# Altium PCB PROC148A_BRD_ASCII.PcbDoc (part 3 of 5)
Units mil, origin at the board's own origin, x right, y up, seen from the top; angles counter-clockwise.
Board outline 7150 x 3764 mil, 4 copper layers (Top Layer, GND01, PWR/GND02, Bottom Layer), stack 60.96 mil thick; 312 components, 352 nets, 2206 pads, 423 vias.
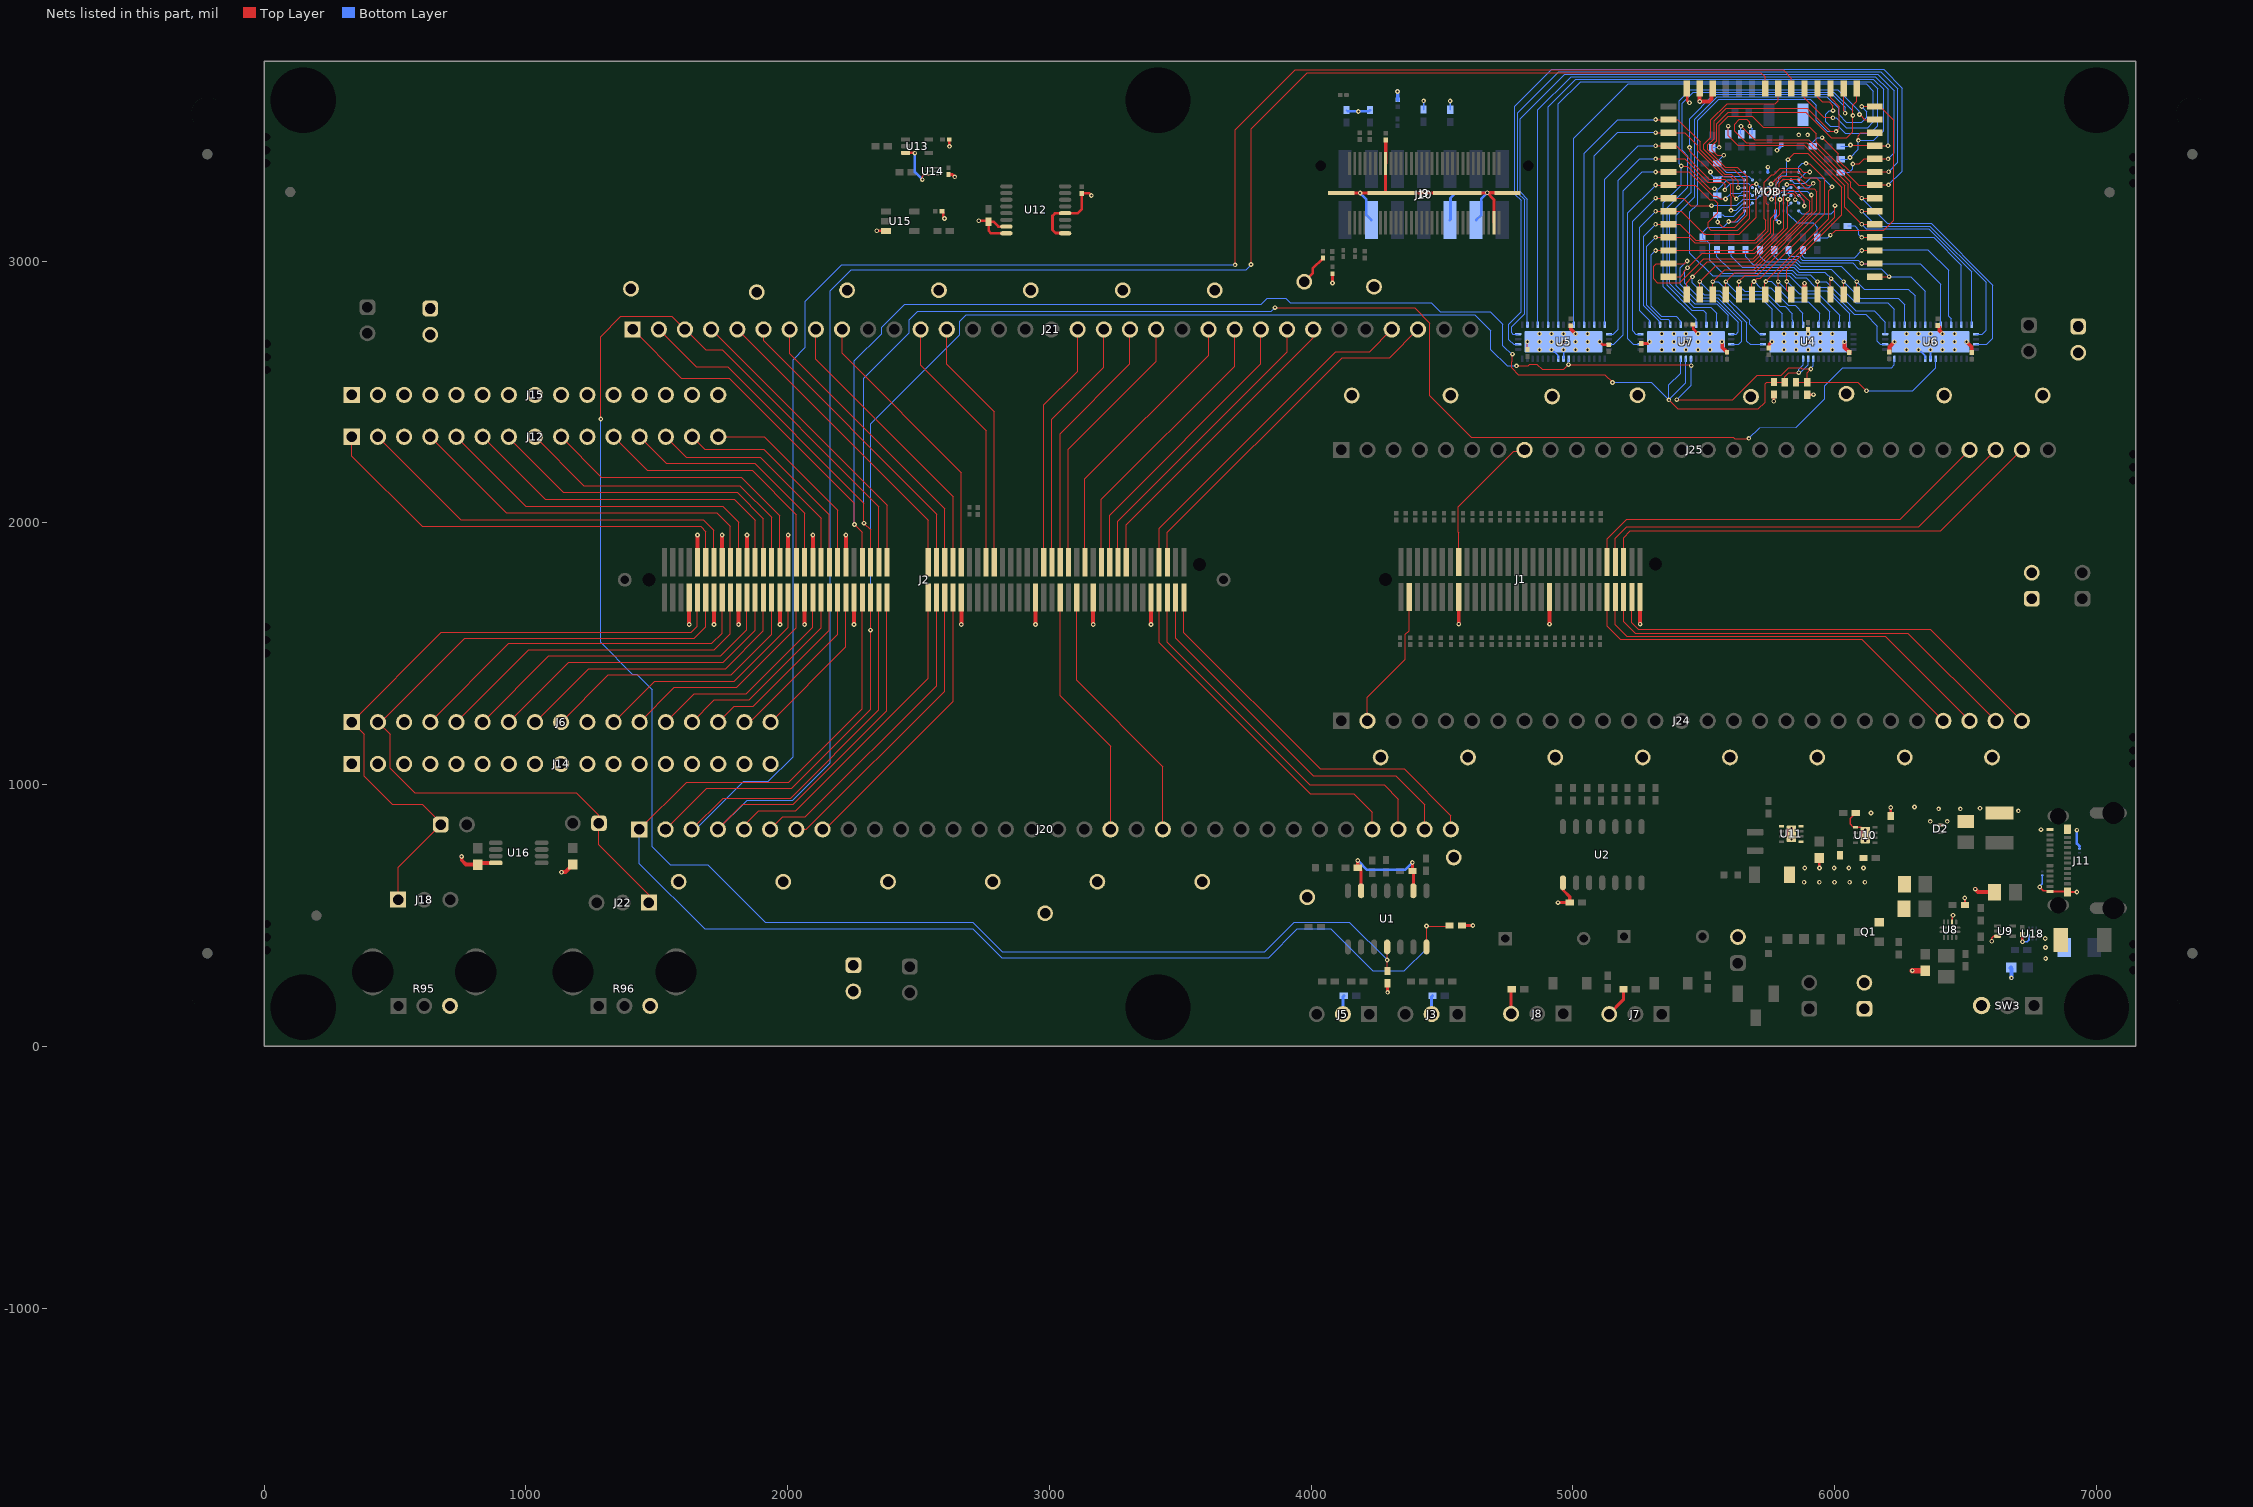
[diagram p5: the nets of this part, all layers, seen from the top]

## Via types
v1: diameter 18, hole 8, Top Layer to Bottom Layer, tented both sides, 422 vias
v2: diameter 18, hole 8, Top Layer to Bottom Layer, 1 vias

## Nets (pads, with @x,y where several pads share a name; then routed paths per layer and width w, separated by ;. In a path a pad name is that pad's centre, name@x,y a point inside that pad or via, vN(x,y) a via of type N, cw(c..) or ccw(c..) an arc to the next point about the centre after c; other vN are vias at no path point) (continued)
GND: C1.2 C2.2 C3.2 C4.2 C5.2 C6.2 C7.2 C8.2 C9.2 C10.2 C11.2 C12.2 C13.2 C14.2 C15.2 C16.2 C17.2 C18.2 C19.2 C20.2 C21.2 C22.2 C23.2 C24.2 C25.2 C26.2 C27.2 C28.2 C29.2 C30.2 C31.2 C32.2 C33.1 C34.1 C35.2 C36.2 C37.2 C38.2 C39.2 C40.2 C41.2 C43.2 C44.2 D2.2 D3.1 D4.1 J1.135 J1.157 J1.179 J2.7 J2.10 J2.13 J2.16 J2.19 J2.22 J2.29 J2.32 J2.35 J2.38 J2.46 J2.47 J2.65 J2.83 J2.97 J2.111 J3.2 J4.2 J5.2 J6.3 J6.10 J7.3 J8.3 J9.16 J9.57 J9.MP1 J9.MP2 J9.MP3 J9.MP4 J10.4 J10.10 J10.12 J11.A1 J11.A12 J11.B1 J11.B12 J12.3 J12.10 J13.1 J13.2 J14.1 J14.2 J14.3 J14.4 J14.5 J14.6 J14.7 J14.8 J14.9 J14.10 J14.11 J14.12 J14.13 J14.14 J14.15 J14.16 J14.17 J15.1 J15.2 J15.3 J15.4 J15.5 J15.6 J15.7 J15.8 J15.9 J15.10 J15.11 J15.12 J15.13 J15.14 J15.15 J17.1 J17.2 J26.1 J26.2 J27.1 J27.2 J30.1 J30.2 J31.1 J32.1 J33.1 J34.1 J35.1 J36.1 J37.1 J38.1 J39.1 J40.1 J41.1 J42.1 J43.1 J44.1 J45.1 J46.1 J47.1 J48.1 J49.1 J50.1 J51.1 J52.1 J53.1 J54.1 J55.1 J56.1 J57.1 J58.1 J59.1 J60.1 J61.1 J62.1 J63.1 J64.1 MOD1.24 MOD1.54 MOD1.55 MOD1.56 Q1.2 R8.1 R9.1 R20.1 R22.1 R25.1 R37.1 R38.1 R39.1 R52.2 R53.1 R57.2 R81.1 R82.1 R93.1 R95.3 R96.3 SW3.3 U1.2 U1.6 U2.8 U3.D1 U3.E6 U4.43 U5.9 U5.10 U5.43 U6.9 U6.10 U6.43 U7.43 U8.10 U9.3 U10.5 U10.9 U11.1 U11.4 U11.5 U11.9@5834.41,812.07 U12.7 U12.8 U12.9 U12.12 U13.3 U14.3 U15.3 U16.4 U18.3 | length 7692.2
  Top Layer w4: v1(4825.93,2691.88) 4825.93,2662.26 C15.2@4826.2,2661.98 ; C13.2@5897.7,2739.41 5898.72,2738.39 v1(5898.72,2722.39)
  Top Layer w6: v1(2514.67,3311.21) 2514.84,3311.38 2514.84,3324.49 2519.9,3329.55 U14.3@2537.8,3329.55 ; C31.2@6080,891.89 6060,871.89 6060,848.37 6069.69,838.69 6077.49,838.69 U10.5@6079.41,836.76 6100.61,836.76 6116.82,820.56 U10.9@6116.82,807.24 ; U8.10@6448.46,475.46 6448.46,494.31 6452,497.84 v1(6452,501) ; v1(6496.94,566.8) 6496.94,565 6497.64,564.3 R53.1@6497.64,540.03 ; v1(6600,402) 6600,413.94 6607.06,421 U9.3@6622,421 ; v1(6783.12,608.74) 6797.06,594.8 6819.02,594.8 J11.A1@6821.93,591.89 6886.89,591.89 J11.B12@6888.86,589.92 v1(6925,589.92)
  Top Layer w10: v1(2340.36,3115.94) 2374.83,3115.94 U15.3@2376.02,3114.75 ; U13.3@2450.71,3413.37 2485.11,3413.37 v1(2485.95,3412.53) ; C40.2@2589.95,3190.55 2590.74,3190.55 2594.01,3187.28 2594.01,3169.83 2598.99,3164.84 v1(2598.99,3162.68) ; C38.2@2617.28,3464.55 2617.76,3464.07 2617.76,3438.94 v1(2618.24,3438.46) ; v1(2730.09,3154.06) 2764.52,3154.06 R82.1@2767.9,3150.68 ; U12.8@2835.71,3106.36 2777.68,3106.36 2767.9,3116.14 R82.1@2767.9,3150.68 ; U12.7@2835.71,3131.95 2805.44,3131.95 2786.71,3150.68 R82.1@2767.9,3150.68 ; U12.9@3060.12,3106.36 3059.02,3107.46 3023.21,3107.46 3011.71,3118.96 3011.71,3172.76 3021.5,3182.55 3059.53,3182.55 U12.12@3060.12,3183.13 3108.85,3183.13 3124.03,3198.31 3124.18,3198.31 C37.2@3124.18,3258.59 3152.57,3258.59 v1(3160.27,3250.89) ; J32.1@3974.04,2921.24 4005.94,2953.14 4005.94,2971.4 4045.41,3010.87 R25.1@4045.41,3011.66 R25.1@4045.81,3011.26 ; v1(4081.37,2916.66) 4081.68,2916.97 C24.2@4081.68,2952.17 ; J31.1@4240.07,2901.87 J31.1@4240.27,2902.07 ; v1(5102.31,2691.88) 5113.65,2680.54 C14.2@5137.39,2680.54 ; C21.2@5261.18,2685.49 5286.84,2685.49 v1(5293.23,2691.88) ; MOD1.56@5434.29,3659.36 5436.69,3656.97 5436.69,3613.86 v1(5445.4,3605.15) ; C22.2@5459.09,2757.6 5459.91,2756.78 5459.91,2739.96 v1(5477.48,2722.39) ; v1(5766.99,2464.61) 5766.99,2489.72 R20.1@5767.99,2490.72 ; R22.1@5896.52,2489.95 R22.1@5896.48,2489.91 ; v1(5918.63,2489.91) R22.1@5896.48,2489.91 ; v1@5940.74,681.74 C33.1@5940.74,720 ; R93.1@6214.01,880.08 v1(6214,913) ; C43.2@6716.04,428.03 6716.62,427.44 6716.62,400.58 v1(6717.21,399.99) ; R22.1@5896.48,2489.91 5895.9,2489.91 5895.9,2489.32 R22.1@5896.48,2489.91
  Top Layer w12: C39.2@2614.29,3331.13 2614.49,3330.92 2629.33,3330.92 v1(2638.5,3321.75) ; J9.MP1@4114.75,3260.09 v1(4187,3260.1) J9.MP2@4281.17,3260.1 ; v1(4178.03,710.13) C2.2@4178.03,682.92 4181.83,682.92 4190.64,674.11 U1.6@4190.64,594.55 ; C23.2@4284.88,3462.56 4284.76,3462.44 4284.76,3373.01 J9.16@4284.63,3372.89 4284.63,3263.56 J9.MP2@4281.17,3260.1 ; R9.1@4291.3,241.38 4291.3,207.6 v1(4292.4,206.5) ; v1(4386.65,703) 4386.92,702.72 C1.2@4386.92,670.72 4390.64,667 U1.2@4390.64,594.55 ; R8.1@4576.02,461.6 v1(4617.7,461.6) ; v1(4672.6,3261) 4748.89,3261 J9.MP4@4749.79,3260.09 ; J9.57@4698.02,3147.3 4698.02,3235.58 4673.5,3260.1 J9.MP3@4557.27,3260.09 4429,3260.1 4428.79,3260.3 4428.59,3260.1 J9.MP2@4307.27,3260.09 J9.MP2@4281.17,3260.1 ; J8.3@4763.69,125 4763.69,216.03 C7.2@4766.38,218.72 ; v1(4943.17,549.33) C5.2@4987.85,549.3 4987.85,571.66 4961.97,597.54 U2.8@4961.97,625.17 ; J7.3@5138.62,123.66 5192.76,177.8 C6.2@5192.76,218.72 ; C12.2@5748.48,2667.84 5748.48,2679.83 v1(5760.53,2691.88)
  Top Layer w15: v1@754.87,725.16 755.21,724.82 755.21,711.14 772.13,694.21 C30.2@816.38,694.21 822.77,700.6 884.64,700.6 U16.4@885.16,701.12 ; v1(1135.84,665.34) 1136.42,665.91 1150.87,665.91 1167.97,683.01 1168.35,683.01 1179.55,694.21 C41.2@1179.55,694.59 ; v1(1624.09,1611.66) J2.7@1624.09,1715.73 ; J2.10@1655.59,1849.59 v1(1655.59,1953.66) ; v1(1718.58,1611.66) J2.13@1718.58,1715.73 ; J2.16@1750.07,1849.59 v1(1750.07,1953.66) ; v1(1813.07,1611.66) J2.19@1813.07,1715.73 ; J2.22@1844.56,1849.59 v1(1844.56,1953.66) ; v1(1970.55,1611.66) J2.29@1970.55,1715.73 ; J2.32@2002.04,1849.59 v1(2002.04,1953.66) ; v1(2065.04,1611.66) J2.35@2065.04,1715.73 ; J2.38@2096.53,1849.59 v1(2096.53,1953.66) ; J2.46@2222.52,1849.59 v1(2222.52,1953.66) ; v1(2254.01,1611.66) J2.47@2254.01,1715.73 ; v1(2663.46,1611.66) J2.65@2663.46,1715.73 ; v1(2946.93,1611.66) J2.83@2946.93,1715.73 ; v1(3167.4,1611.66) J2.97@3167.4,1715.73 ; v1(3387.87,1611.66) J2.111@3387.87,1715.73 ; v1(4563.78,1613) J1.135@4563.78,1717.07 ; v1(4910.24,1613) J1.157@4910.24,1717.07 ; C16.2@4991.7,2753.41 4991.7,2740.87 v1(5010.18,2722.39) ; v1(5256.69,1613) J1.179@5256.69,1717.07 ; MOD1.55@5484.29,3659.36 v1(5484.29,3609.71) 5484.65,3609.35 5520.64,3609.35 5529.79,3618.5 5529.79,3654.86 MOD1.54@5534.29,3659.36 ; v1(5569.61,2691.88) 5570.5,2690.99 5570.5,2670.48 5588.8,2652.18 C20.2@5588.8,2651.39 ; MOD1.24@5884.29,2871.96 5884.37,2872.05 v1(5884.37,2915.4) ; v1(6036.91,2691.88) 6037.8,2690.99 6037.8,2670.48 6056.1,2652.18 C11.2@6056.1,2651.39 ; C18.2@6208.54,2652.91 6208.54,2672.59 v1(6227.83,2691.88) ; C19.2@6393.6,2753.41 6399.87,2747.14 6399.87,2734.61 v1(6412.08,2722.39) ; v1(6504.21,2691.88) 6523.4,2672.69 C17.2@6523.4,2651.39 ; v1(6537.05,601) 6548.13,589.92 C26.2@6610,589.92
  Top Layer w20: v1(6296.63,289.52) 6297.45,288.7 R52.2@6346,288.7
  Bottom Layer w6: R39.1@4134.6,3577 R39.1@4139.73,3571.87 ; R37.1@4429.6,3579.24 v1(4429.6,3612.24) ; R81.1@4531,3578.7 v1(4531,3611.7) ; v1(4918.05,2661.37) 4921.25,2661.37 4942.51,2640.12 4942.51,2628.84 U5.10@4944.43,2626.92 ; U5.9@4964.12,2626.92 v1(4964.12,2661.37) ; v1(6319.96,2661.37) 6323.16,2661.37 6344.41,2640.12 6344.41,2628.84 U6.10@6346.34,2626.92 ; U6.9@6366.02,2626.92 v1(6366.02,2661.37) ; v1(6717.21,399.99) 6735.51,399.98 6741.67,406.14 6741.67,406.68 6742.18,407.19 U18.3@6742.18,415.65 ; v1(6783.12,608.74) 6783.12,611.99 6792.77,621.63 D3.1@6792.77,653.8
  Bottom Layer w7: D4.1@6935,755 6935,765.1
  Bottom Layer w10: v1(2485.95,3412.53) 2485.95,3339.93 v1(2514.67,3311.21) ; R39.1@4139.73,3571.87 v1(4180.13,3571.87) 4219.47,3571.87 R38.1@4224.6,3577 ; v1(4178.03,710.13) 4213.3,674.85 4358.5,674.85 v1(4386.65,703) ; v1(4187,3260.1) 4210.84,3236.25 4210.84,3175.92 J10.4@4230,3156.76 ; J10.10@4530,3156.76 4532.4,3159.16 4532.4,3240.33 4553.82,3261.75 4673.35,3261.75 v1(4672.6,3261) 4650,3238.4 4650,3176.76 J10.12@4630,3156.76 ; U3.D1@5744.53,3339.53 v1(5744.53,3358.93) ; U3.E6@5774.06,3191.89 5774.06,3161.79 v1(5787.22,3148.62) ; v1(6925,826.14) 6925,775.1 6935,765.1
  Bottom Layer w12: J5.2@4121.41,123.67 4121.41,190.31 C4.2@4124.78,193.67 ; J3.2@4459.94,123.67 4459.94,190.31 C3.2@4463.3,193.67 ; v1@5779.45,3423.67 5793.01,3437.23 5793.01,3442.51 C9.2@5795.28,3444.78
  Bottom Layer w15: v1(4329.7,3647.59) 4329.7,3646.78 4330.71,3645.77 C25.2@4330.71,3616.12 ; C44.2@6674.01,302 6671.66,299.65 6674.81,296.5 v1(6674.81,262.18)
  other v1: 6805.94,335.79 6805.12,378.11 6804.15,412.02 5883.4,627.24 5941.3,627.24 5999.2,627.24 6057.1,627.24 6115,627.24 5885.74,681.74 5941.81,681.74 5997.87,681.74 6053.94,681.74 6110,681.74 754.78,725.25 6116.82,785.58 5834.41,790.42 6788.01,828.11 6116.82,828.89 5834.41,833.73 6365,860 6430,860 6138.86,891.89 6701.38,900 6397.12,907.5 6480,907.5 6555,910 6305,915 4871.99,2661.37 5010.18,2661.37 5056.24,2661.37 5339.29,2661.37 5385.35,2661.37 5431.42,2661.37 5477.48,2661.37 5523.54,2661.37 5806.59,2661.37 5852.66,2661.37 5898.72,2661.37 5944.78,2661.37 5990.85,2661.37 6273.89,2661.37 6412.08,2661.37 6458.15,2661.37 4871.99,2691.88 4918.05,2691.88 4964.12,2691.88 5010.18,2691.88 5056.24,2691.88 5339.29,2691.88 5385.35,2691.88 5431.42,2691.88 5477.48,2691.88 5523.54,2691.88 5806.59,2691.88 5852.66,2691.88 5898.72,2691.88 5944.78,2691.88 5990.84,2691.88 6273.89,2691.88 6319.96,2691.88 6366.02,2691.88 6412.08,2691.88 6458.15,2691.88 4871.99,2722.39 4918.05,2722.39 4964.12,2722.39 5056.24,2722.39 5339.29,2722.39 5385.35,2722.39 5431.42,2722.39 5523.54,2722.39 5806.59,2722.39 5852.66,2722.39 5944.78,2722.39 5990.85,2722.39 6273.89,2722.39 6319.96,2722.39 6366.02,2722.39 6458.15,2722.39 5779.43,3423.67 5862.55,3482.45 5896.58,3482.45
GPIO48_MUX: MOD1.49 R78.1 U3.A6 U6.19 | length 2019.2
  Top Layer w4: v1(5594.8,3150.96) 5615.96,3150.96 5654.9,3189.9 5654.9,3311 5617,3348.9 5578.05,3348.9 5500.2,3426.75 5500.2,3446.06 5527.3,3473.16 5527.3,3539.89 5588.78,3601.37 5772.23,3601.37 5784.29,3613.43 MOD1.49@5784.29,3659.36
  Bottom Layer w4: U3.A6@5655.94,3191.89 5655.94,3178.7 5628.21,3150.96 v1(5594.8,3150.96) 5573.77,3129.93 5514.59,3129.93 5495.22,3110.56 5495.22,3087.76 5505.03,3077.95 5510.69,3077.95 5522.22,3066.42 5522.22,3003.72 5571.95,2953.99 5833.75,2953.99 5850.89,2936.85 5890.47,2936.85 5926.42,2900.9 5969.47,2900.9 6074.14,2796.23 6118.58,2796.23 6163.28,2751.53 6163.28,2693.22 6173.5,2683 6191.83,2683 U6.19@6192.79,2682.04
GPIO91: J1.123 J24.2 | length 539.3
  Top Layer w4: J24.2@4215,1244 4215,1333.95 4360.23,1479.18 4360.23,1574.13 4374.8,1588.7 J1.123@4374.8,1717.07
GPMC0_A0_MUX: MOD1.2 U3.A3 U5.34 | length 1461.5
  Top Layer w4: v1(5315.93,3540.66) 5401.27,3540.66 5486.84,3455.09 5486.84,3425.32 5579.56,3332.6 5604.8,3332.6 5631.7,3305.7 v1(5631.7,3280.6)
  Bottom Layer w4: U5.34@5042.86,2756.84 5042.86,3412.06 5171.46,3540.66 v1(5315.93,3540.66) ; v1(5631.7,3280.6) 5631.76,3280.54 U3.A3@5655.94,3280.47 U3.A3@5655.94,3280.47
GPMC0_A1_MUX: MOD1.3 U3.A4 U5.36 | length 1413.4
  Top Layer w4: v1(5315.93,3490.66) 5426.72,3490.66 5476.38,3441.01 5476.38,3422.41 5576.19,3322.6 5600.53,3322.6 5612.01,3311.13 5612.01,3250.07 5623.67,3238.41 v1(5624.2,3237.88)
  Bottom Layer w4: U5.36@5082.23,2756.84 5082.23,3402.13 5171.9,3491.8 5314.8,3491.8 v1(5315.93,3490.66) ; v1(5624.2,3237.88) 5637.27,3250.94 U3.A4@5655.94,3250.94
GPMC0_A2_MUX: MOD1.4 U3.A5 U5.38 | length 1313.1
  Top Layer w4: v1(5315.93,3440.66) MOD1.4@5365.59,3440.66 MOD1.4@5382.03,3440.66 ; MOD1.4@5382.07,3440.7 5394.53,3440.7 5521.63,3313.6 5580.9,3313.6 5602.2,3292.3 5602.2,3247.15 5604.72,3244.63 5604.72,3194.72 v1(5604.1,3194.1)
  Bottom Layer w4: U5.38@5121.6,2756.84 5121.6,3311.8 5250.46,3440.66 v1(5315.93,3440.66) ; v1(5604.1,3194.1) 5622.83,3194.1 5623.67,3194.94 5648.67,3219.94 5654.47,3219.94 U3.A5@5655.94,3221.42
GPMC0_A3_MUX: MOD1.5 U3.B3 U5.39 | length 1238.4
  Top Layer w4: v1(5315.93,3390.66) MOD1.5@5365.59,3390.66 5426.75,3390.66 5515.8,3301.61 5571.82,3301.61 5581.3,3292.13 5581.3,3272.98 v1(5580.48,3272.15)
  Bottom Layer w4: U5.39@5137.34,2721.41 5153.21,2721.41 5172.3,2740.5 5172.3,3308.2 5255.2,3391.1 5315.5,3391.1 v1(5315.93,3390.66) ; v1(5580.48,3272.15) 5580.48,3273.92 5603.55,3297 5668.94,3297 U3.B3@5685.47,3280.47
GPMC0_A4_MUX: MOD1.6 U3.B4 U5.41 | length 1203.8
  Top Layer w4: v1(5315.93,3340.66) MOD1.6@5365.59,3340.66 5443,3340.66 5535.92,3247.74 5549.87,3247.74 5559.94,3237.67 v1(5582.77,3237.67)
  Bottom Layer w4: U5.41@5137.34,2682.04 5155.64,2682.04 5193,2719.4 5193,3268.8 5264.86,3340.66 v1(5315.93,3340.66) ; v1(5582.77,3237.67) 5605.03,3259.94 5640.69,3259.94 5647.11,3266.36 5670.23,3266.36 5685.47,3251.12 U3.B4@5685.47,3250.94
GPMC0_A5_MUX: MOD1.7 U3.C3 U7.19 | length 1416
  Top Layer w4: v1(5315.93,3290.67) MOD1.7@5365.59,3290.66 5466.97,3290.67 5523.37,3234.27 5539.96,3234.27 5552.93,3221.29 5552.93,3183.97 5516.5,3147.54 5516.5,3128.5 5527.3,3117.7 5630.3,3117.7 5676.34,3163.74 5676.34,3170 5676.34,3284.65 5685.8,3294.11 5700.05,3294.11 v1(5700.8,3294.87)
  Bottom Layer w4: U7.19@5258.19,2682.04 5230.86,2682.04 5209.17,2703.73 5209.17,3183.9 v1(5315.93,3290.67) ; v1(5700.8,3294.87) 5700.8,3294.77 5715,3280.57 U3.C3@5715,3280.47
GPMC0_A6_MUX: MOD1.8 U3.C4 U7.21 | length 1005.3
  Top Layer w4: v1(5315.93,3240.67) MOD1.8@5365.59,3240.66 5420.93,3240.67 5449.7,3211.9 v1(5529.4,3211.9)
  Bottom Layer w4: U7.21@5258.19,2721.41 5240.87,2721.41 5228.27,2734.01 5228.27,3153 v1(5315.93,3240.67) ; v1(5529.4,3211.9) 5530.47,3212.97 5626.64,3212.97 5650.47,3236.8 5700.86,3236.8 U3.C4@5715,3250.94
GPMC0_A7_MUX: MOD1.9 U3.D4 U7.23 | length 1071.9
  Top Layer w4: v1(5315.93,3190.67) MOD1.9@5365.59,3190.66 5413.93,3190.67 5501.4,3103.2 5634.8,3103.2 5699.4,3167.8 v1(5699.4,3266.7)
  Bottom Layer w4: U7.23@5293.62,2756.84 5293.62,2772.5 5255.2,2810.92 5255.2,3129.93 v1(5315.93,3190.67) ; v1(5699.4,3266.7) 5728.77,3266.7 U3.D4@5744.53,3250.94
GPMC0_A8_MUX: MOD1.10 U3.H2 U7.25 | length 1330
  Top Layer w4: v1(5315.93,3140.67) MOD1.10@5365.59,3140.66 5408.13,3140.67 5468.6,3080.2 5695.27,3080.2 5736.17,3121.1 5736.17,3156.69 5730.92,3161.94 5730.92,3302.06 5759.29,3330.43 5767.56,3330.43 5791.14,3354.02 5865.78,3354.02 5880.75,3339.05 5903.68,3339.05 v1(5904.73,3340.1)
  Bottom Layer w4: v1(5315.93,3140.67) 5270.98,3095.72 5270.98,2829.82 5330.44,2770.36 5330.44,2759.39 U7.25@5332.99,2756.84 ; U3.H2@5862.64,3310 5891.69,3339.05 5903.68,3339.05 v1(5904.73,3340.1)
GPMC0_A9_MUX: MOD1.11 U3.H3 U7.27 | length 1300.8
  Top Layer w4: v1(5315.93,3090.67) MOD1.11@5365.59,3090.66 5443.99,3090.67 5464.46,3070.2 5700.88,3070.2 5745.91,3115.22 5745.91,3215.06 5739.32,3221.64 5739.32,3256.94 5755.98,3273.6 5767.99,3273.6 5777.26,3282.88 5777.26,3302.06 5799.08,3323.88 5859.57,3323.88 5894.45,3289 5908.67,3289 5916.89,3297.22 v1(5918.02,3297.22)
  Bottom Layer w4: v1(5315.93,3090.67) 5282.8,3057.53 5282.8,2830.73 5335,2778.53 5363.64,2778.53 5370.81,2771.36 5370.81,2758.39 U7.27@5372.36,2756.84 ; U3.H3@5862.64,3280.47 5901.27,3280.47 v1(5918.02,3297.22)
GPMC0_A10_MUX: MOD1.12 U3.H4 U7.29 | length 1190
  Top Layer w4: v1(5315.93,3040.67) MOD1.12@5365.59,3040.66 5687.88,3040.67 5754.91,3107.7 5754.91,3163.64 5761.27,3170 5775.19,3183.92 5775.19,3248.91 5797.07,3270.79 5841.33,3270.79 5884.09,3228.03 v1(5884.09,3210.25)
  Bottom Layer w4: v1(5315.93,3040.67) 5298.77,3023.51 5298.77,2827.48 5337.73,2788.53 5393.87,2788.53 5411.73,2770.67 U7.29@5411.73,2756.84 ; U3.H4@5862.64,3250.94 5884.09,3229.49 v1(5884.09,3210.25)
GPMC0_A11_MUX: MOD1.13 U3.H5 U7.39 | length 1433.3
  Top Layer w4: v1(5436.5,3000.8) 5436.37,3000.67 5435.42,3000.67 5425.42,2990.67 MOD1.13@5365.59,2990.67 5317.77,2990.67 5308.4,2981.3 5308.4,2931.8 5322.6,2917.6 5407.4,2917.6 5499.02,3009.22 5689.7,3009.22 5806.1,3125.61 5806.1,3170 5806.1,3247.74 5817.45,3259.09 5839.9,3259.09 5849.3,3249.7 v1(5849.3,3234.76)
  Bottom Layer w4: v1(5436.5,3000.8) 5410.67,2974.97 5410.67,2910.96 5472.43,2849.2 5550.1,2849.2 5632.15,2767.15 5632.15,2729.36 5624.2,2721.41 U7.39@5604.65,2721.41 ; v1(5849.3,3234.76) U3.H5@5862.64,3221.42
GPMC0_A12_MUX: MOD1.14 U3.G3 U7.41 | length 1151.4
  Top Layer w4: MOD1.14@5365.59,2940.67 5411.07,2940.67 5423.1,2952.7 5423.1,2959.99 v1(5437.81,2974.7) ; v1@5438.68,2973.83 5438.68,2975.57 5493.77,3030.67 5694.49,3030.67 5767,3103.18 5767,3155.09 5790.98,3179.07 v1(5790.98,3235.55)
  Bottom Layer w4: v1(5437.81,2974.7) 5427.29,2964.18 5427.29,2915.71 5482.04,2860.96 5553.12,2860.96 5644.83,2769.24 5644.83,2693.63 5633.24,2682.04 U7.41@5604.65,2682.04 ; v1(5790.98,3235.55) 5790.98,3257.13 5799.63,3265.78 5811.46,3265.78 5825.25,3279.57 5832.21,3279.57 U3.G3@5833.11,3280.47
GPMC0_A13_MUX: MOD1.15 U3.G4 U4.19 | length 1084.1
  Top Layer w4: MOD1.15@5434.29,2871.96 5434.3,2917.81 5454.38,2937.89 v1@5454.38,2942.05 ; v1(5456.46,2939.97) v1@5454.38,2942.05 ; v1(5821.4,3236.8) 5821.4,3128.19 5690.03,2996.82 5513.31,2996.82 5458.54,2942.05 v1@5454.38,2942.05
  Bottom Layer w4: v1(5456.46,2939.97) 5456.46,2917.05 5502.56,2870.96 5558.76,2870.96 5664.84,2764.89 5664.84,2693.68 5676.48,2682.04 U4.19@5725.49,2682.04 ; v1(5821.4,3236.8) 5821.4,3239.23 U3.G4@5833.11,3250.94
GPMC0_A14_MUX: MOD1.16 U3.F3 U4.21 | length 1081.3
  Top Layer w4: MOD1.16@5484.29,2871.96 v1(5484.29,2921.62) 5545.02,2982.35 5692.27,2982.35 5879.93,3170 5890,3180.07 5904.27,3194.34 5904.27,3227.88 5890,3242.15 5839.16,3292.98 v1(5817.17,3292.98)
  Bottom Layer w4: v1(5484.29,2921.62) 5518.79,2887.12 5561.39,2887.12 5674.84,2773.68 5674.84,2759.7 5713.13,2721.41 U4.21@5725.49,2721.41 ; U3.F3@5803.58,3280.47 5804.57,3280.47 5817.08,3292.98 v1(5817.17,3292.98)
GPMC0_A15_MUX: MOD1.17 U3.F4 U4.23 | length 1052.7
  Top Layer w4: MOD1.17@5534.29,2871.96 v1(5534.29,2921.62) 5579.51,2966.84 5690.91,2966.84 5913.27,3189.2 5913.27,3249.86 v1(5910.65,3252.48)
  Bottom Layer w4: v1(5534.29,2921.62) 5554.45,2921.62 5620.49,2855.58 5721.72,2855.58 5760.92,2816.38 U4.23@5760.92,2756.84 ; U3.F4@5803.58,3250.94 5813.41,3250.94 5828.67,3266.2 5890,3266.2 5895.86,3266.2 5909.59,3252.48 v1(5910.65,3252.48)
GPMC0_A16_MUX: MOD1.18 U3.E4 U4.25 | length 1155.3
  Top Layer w4: MOD1.18@5584.29,2871.96 v1(5584.3,2921.5) 5618.27,2955.47 5693.68,2955.47 5932.12,3193.91 5932.12,3264.69 5921.3,3275.51 5890,3275.51 5889.73,3275.51 5852.62,3312.62 5803.69,3312.62 5788.02,3296.95 5788.02,3277.3 5759.18,3248.45 5759.18,3236.23 v1(5758.85,3235.8)
  Bottom Layer w4: v1(5584.3,2921.5) 5633.84,2871.97 5727.84,2871.97 5800.29,2799.51 U4.25@5800.29,2756.84 ; v1@5758.88,3235.8 U3.E4@5774.03,3250.94
GPMC0_A17_MUX: MOD1.19 U3.D3 U4.27 | length 1137.8
  Top Layer w4: MOD1.19@5634.29,2871.96 v1(5634.3,2921.5) 5634.3,2922.51 5658.22,2946.43 5703.58,2946.43 5945.28,3188.13 5945.28,3303.3 5929.92,3318.66 5883.74,3318.66 5860.96,3341.44 5802.52,3341.44 5756.9,3295.82 v1(5756.9,3294.87)
  Bottom Layer w4: v1(5634.3,2921.5) 5634.3,2905.26 5655.46,2884.1 5733.37,2884.1 5789.84,2827.63 5810.55,2827.63 5838.47,2799.7 5838.47,2776.03 5839.66,2774.84 U4.27@5839.66,2756.84 ; U3.D3@5744.53,3280.47 5756.9,3292.85 v1(5756.9,3294.87)
GPMC0_A18_MUX: MOD1.20 U3.H1 U4.29 | length 995
  Top Layer w4: MOD1.20@5684.29,2871.96 5684,2872.26 5684,2912.93 5691.75,2920.67 v1(5691.75,2922.27) ; v1@5692.59,2922.27 5704.6,2934.28 5715.18,2934.28 5962.11,3181.21 5962.11,3314.97 5905.16,3371.92 5891.65,3371.92 v1(5890.16,3373.41)
  Bottom Layer w4: v1(5691.75,2922.27) 5715.63,2898.39 5755.78,2898.39 5823.21,2830.96 5848.38,2830.96 5878.63,2800.71 5878.63,2757.25 U4.29@5879.03,2756.84 ; U3.H1@5862.64,3339.53 5862.64,3359.74 5876.31,3373.41 v1(5890.16,3373.41)
GPMC0_A19_MUX: MOD1.21 U3.G2 U4.32 | length 1007.4
  Top Layer w4: MOD1.21@5734.29,2871.96 5732.99,2873.27 5732.99,2914.62 5736.85,2918.48 v1(5736.85,2922.27) 5976.74,3162.16 5976.74,3269.57 5989.75,3282.57 v1(5989.75,3283.87)
  Bottom Layer w4: v1(5736.85,2922.27) 5756.84,2922.27 5834.81,2844.3 5899.69,2844.3 5943.36,2800.64 5943.36,2776.71 5941.01,2774.37 5941.01,2759.76 U4.32@5938.09,2756.84 ; U3.G2@5833.11,3310 5846.11,3297 5887,3297 5909.04,3319.04 5953.41,3319.04 5988.58,3283.87 v1(5989.75,3283.87)
GPMC0_A20_MUX: MOD1.22 U3.H6 U4.34 | length 890.8
  Top Layer w4: MOD1.22@5784.29,2871.96 v1(5784.3,2921.5) 5784.3,2951.75 6000.88,3168.34 v1(6000.88,3211.88)
  Bottom Layer w4: v1(5784.3,2921.5) 5845.9,2859.9 5926.89,2859.9 5981.1,2805.69 5981.1,2777.89 5977.87,2774.65 5977.87,2757.25 U4.34@5977.46,2756.84 ; U3.H6@5862.64,3191.89 5862.98,3191.89 5874.57,3180.3 5986.24,3180.3 6000.88,3194.95 v1(6000.88,3211.88)
GPMC0_A21_MUX: MOD1.23 U3.E3 U4.36 | length 1203.9
  Top Layer w4: v1(5821.5,3387.7) 5845.86,3412.06 5897.55,3412.06 6026.87,3282.74 6026.87,3177.19 5816.8,2967.12 v1(5816.8,2922.27) 5816.8,2889.47 MOD1.23@5834.29,2871.96
  Bottom Layer w4: U3.E3@5774.06,3280.47 5775.13,3281.55 5775.13,3292.33 5787.2,3304.4 5787.2,3317.68 5795.01,3325.49 5812.14,3325.49 5817.37,3330.72 5817.37,3379.78 5821.5,3383.91 v1(5821.5,3387.7) ; v1(5816.8,2922.27) 5864.56,2874.51 5937.87,2874.51 6018.88,2793.51 ; U4.36@6016.83,2756.84 6018.88,2758.89 6018.88,2777.87 ; 6018.86,2777.89 6018.86,2793.49
GPMC0_AD0_MUX: MOD1.25 R12.2 U6.21 | length 867.3
  Top Layer w4: MOD1.25@5934.29,2871.96 v1(5934.29,2921.62)
  Bottom Layer w4: R12.2@5550.01,3042.66 5550.01,3017.36 5602.07,2965.31 5837.24,2965.31 5854.77,2947.77 5907.41,2947.77 5933.56,2921.62 5967.78,2921.62 6079.96,2809.44 6150.76,2809.44 6192.79,2767.41 U6.21@6192.79,2721.41
GPMC0_AD1_MUX: MOD1.26 R48.2 U6.23 | length 856.8
  Top Layer w4: MOD1.26@5984.29,2871.96 5982.38,2873.87 5982.38,2925.17 5986.55,2929.35 v1(5986.55,2933.13)
  Bottom Layer w4: R48.2@5604.8,3042.66 5604.8,3017.75 5646.65,2975.9 5843.7,2975.9 5861.83,2957.77 5961.92,2957.77 v1@5987.78,2931.91 ; v1(5986.55,2933.13) 5987.99,2933.13 6079.52,2841.6 6203.1,2841.6 6228.22,2816.48 U6.23@6228.22,2756.84
GPMC0_AD2_MUX: MOD1.27 R59.2 U6.25 | length 836.8
  Top Layer w4: MOD1.27@6034.29,2871.96 v1(6034.29,2921.62)
  Bottom Layer w4: R59.2@5659.59,3042.66 5659.59,3015.91 5688.46,2987.03 5847.32,2987.03 5864.86,2969.49 5986.42,2969.49 v1(6034.29,2921.62) 6097.71,2858.2 6243.2,2858.2 6267.6,2833.8 U6.25@6267.6,2756.84
GPMC0_AD3_MUX: MOD1.28 R60.2 U6.27 | length 838.8
  Top Layer w4: MOD1.28@6084.29,2871.96 v1(6084.29,2921.62)
  Bottom Layer w4: R60.2@5714.38,3042.66 5714.38,3019.13 5735.7,2997.8 5851.1,2997.8 5867.92,2980.98 6024.93,2980.98 v1(6084.29,2921.62) 6113.71,2892.2 6281.6,2892.2 6306.97,2866.84 U6.27@6306.97,2756.84
GPMC0_AD4_MUX: MOD1.29 R61.2 U6.29 | length 839.7
  Top Layer w4: MOD1.29@6152.99,2940.66 6153.06,2940.6 v1(6208.1,2940.6)
  Bottom Layer w4: R61.2@5769.17,3042.66 5769.17,3018.67 5780.04,3007.8 5854.39,3007.8 5868.71,2993.48 6069.14,2993.48 6090.83,2971.79 6176.91,2971.79 v1(6208.1,2940.6) 6290.5,2940.6 6346.34,2884.76 U6.29@6346.34,2756.84
GPMC0_AD5_MUX: MOD1.30 R62.2 U6.32 | length 851.8
  Top Layer w4: v1(6103.33,2990.67) MOD1.30@6152.99,2990.66
  Bottom Layer w4: R62.2@5823.95,3042.66 5823.95,3022.76 5828.92,3017.8 5862.07,3017.8 5876.16,3003.72 6090.28,3003.72 v1(6103.33,2990.67) 6326.33,2990.67 6405.39,2911.61 U6.32@6405.39,2756.84
GPMC0_AD6_MUX: MOD1.31 R63.2 U6.34 | length 889.6
  Top Layer w4: v1(6103.33,3040.67) MOD1.31@6152.99,3040.66
  Bottom Layer w4: R63.2@5878.74,3042.66 5878.74,3019.01 5884.34,3013.42 6076.09,3013.42 v1(6103.33,3040.67) 6162.87,3040.67 6166.2,3044 6356.3,3044 6435.74,2964.56 6435.74,2789.79 6444.76,2780.77 U6.34@6444.76,2756.84
GPMC0_AD7_MUX: MOD1.32 R64.2 U6.36 | length 785.1
  Top Layer w4: v1(6103.33,3090.67) MOD1.32@6152.99,3090.66
  Bottom Layer w4: R64.2@6048.9,3134.19 6077.21,3134.19 6092.73,3118.67 6092.73,3101.27 v1(6103.33,3090.67) 6378.51,3090.67 6484.13,2985.04 U6.36@6484.13,2756.84
GPMC0_AD8_MUX: MOD1.33 R65.2 U6.38 | length 1513.2
  Top Layer w4: v1(5593.26,3515.49) 5593.26,3479.41 5630.13,3442.55 5883.89,3442.55 6038.9,3287.53 6038.9,3205.1 v1(6103.33,3140.67) MOD1.33@6152.99,3140.66
  Bottom Layer w4: v1(5593.26,3515.49) 5593.26,3485.2 R65.2@5593.58,3484.87 ; v1(6103.33,3140.67) 6120.3,3123.7 6359.62,3123.7 6523.5,2959.82 U6.38@6523.5,2756.84
GPMC0_AD9_MUX: MOD1.34 R66.2 U6.39 | length 1656.1
  Top Layer w4: v1(5675.28,3515.49) 5675.28,3531.17 5664.6,3541.86 5635.65,3541.86 5617.39,3523.6 5617.39,3496.46 5661.3,3452.55 5893.49,3452.55 6051.9,3294.14 6051.9,3242.1 v1(6103.33,3190.67) MOD1.34@6152.99,3190.66
  Bottom Layer w4: v1(5675.28,3515.49) 5684.94,3505.83 R66.2@5684.94,3485.14 ; v1(6103.33,3190.67) 6160.3,3133.7 6363.76,3133.7 6578.84,2918.62 6578.84,2736.29 6563.96,2721.41 U6.39@6539.25,2721.41
GPMC0_AD10_MUX: MOD1.35 R67.2 U6.41 | length 1583.7
  Top Layer w4: v1(5641.67,3515.03) 5642.59,3515.03 5694.7,3462.92 5900.59,3462.92 6061.9,3301.61 6061.9,3282.1 v1(6103.33,3240.67) MOD1.35@6152.99,3240.66
  Bottom Layer w4: v1(5641.67,3515.03) 5641.67,3486.48 R67.2@5643.28,3484.87 ; v1(6103.33,3240.67) 6103.33,3240.32 6199.96,3143.7 6367.9,3143.7 6604.5,2907.1 6604.5,2704.9 6581.64,2682.04 U6.41@6539.25,2682.04
GPMC0_AD11_MUX: MOD1.36 R68.2 U5.19 | length 3825.2
  Top Layer w4: v1(5558.79,3434.57) 5558.79,3518.9 5594.05,3554.16 5684.4,3554.16 5727.22,3511.34 5905.02,3511.34 5929.14,3487.23 5929.14,3453.62 6092.1,3290.67 MOD1.36@6152.99,3290.66 6153.82,3291.5 v1(6205.1,3291.5)
  Bottom Layer w4: U5.19@4790.89,2682.04 4790.71,2682.22 4773.08,2682.22 4755.67,2699.63 4755.67,2758.67 4802.8,2805.8 4802.8,3231.58 4778.58,3255.8 4778.58,3592.2 4918.38,3732 6186.86,3732 6257.69,3661.17 6257.69,3344.09 v1(6205.1,3291.5) ; R68.2@5531.88,3431.21 5535.24,3434.57 v1(5558.79,3434.57)
GPMC0_AD12_MUX: MOD1.37 R69.2 U5.21 | length 3155.4
  Top Layer w4: v1(5952.1,3471.8) 6014.08,3409.83 6014.08,3385.7 6059.11,3340.67 MOD1.37@6152.99,3340.66 6153.82,3341.5 v1(6206.1,3341.5)
  Bottom Layer w4: U5.21@4790.89,2721.41 4770.69,2721.41 4765.67,2726.43 4765.67,2749.27 4815,2798.6 4815,3233.52 4788.58,3259.94 4788.58,3566.08 4945.5,3723 6176.09,3723 6241.4,3657.69 6241.4,3376.8 v1(6206.1,3341.5) ; R69.2@5916.11,3438.83 5916.25,3438.97 5916.25,3454.3 5933.76,3471.8 v1(5952.1,3471.8)
GPMC0_AD13_MUX: MOD1.38 R70.2 U5.23 | length 2806.8
  Top Layer w4: v1(6069.35,3371.38) 6093.53,3371.38 6112.81,3390.67 MOD1.38@6152.99,3390.66 6153.12,3390.8 v1(6204.1,3390.8)
  Bottom Layer w4: U5.23@4826.32,2756.84 4826.32,3236.34 4798.58,3264.08 4798.58,3543.82 4968.76,3714 6165.14,3714 6227.5,3651.64 6227.5,3414.2 v1(6204.1,3390.8) ; R70.2@6023.44,3339.05 6054.96,3339.05 6069.35,3353.44 v1(6069.35,3371.38)
GPMC0_AD14_MUX: MOD1.39 R71.2 U5.25 | length 2630.5
  Top Layer w4: v1(6060.2,3443.42) 6061.23,3442.39 6151.27,3442.39 MOD1.39@6152.99,3440.66 ; MOD1.39@6152.99,3440.66 v1(6203.6,3440.7)
  Bottom Layer w4: U5.25@4865.69,2756.84 4865.69,3577.7 4992.99,3705 6154.6,3705 6203.6,3656 v1(6203.6,3440.7) ; R71.2@6023.46,3438.29 6023.89,3438.73 6051.72,3438.73 6056.41,3443.42 v1(6060.2,3443.42)
GPMC0_AD15_MUX: MOD1.40 R72.2 U5.27 | length 2646.1
  Top Layer w4: v1(6090.34,3461.26) 6090.34,3479.78 6100.31,3489.75 6152.07,3489.75 MOD1.40@6152.99,3490.66
  Bottom Layer w4: U5.27@4905.06,2756.84 4905.06,3589.06 5011,3695 6147.43,3695 6186.75,3655.68 6186.75,3498.55 6149.46,3461.26 v1(6090.34,3461.26) 6090.34,3427.19 v1(6058.64,3395.48) 6054.85,3395.48 6048.25,3388.88 R72.2@6022.89,3388.88
GPMC0_BE0N_CLE_MUX: MOD1.43 R76.1 U3.A1 U7.34 | length 2775.8
  Top Layer w4: v1(5576.28,3404.55) 5550.86,3404.55 5532.21,3423.2 5532.21,3442.87 5548.74,3459.41 5548.74,3525.27 5592.71,3569.24 5888.83,3569.24 5987.57,3470.49 6046.93,3470.49 6069.7,3493.26 6069.7,3555.99 v1(6069.13,3556.55) 6069.13,3595.13 6084.29,3610.29 MOD1.43@6084.29,3659.36
  Bottom Layer w4: U7.34@5510.16,2756.84 5510.16,2801.34 5498.42,2813.08 5454.16,2813.08 5359.88,2907.36 5359.88,3204.07 5438.56,3282.75 5438.56,3400.69 5416.65,3422.6 5416.65,3603.1 5459.56,3646 5995.57,3646 6068.02,3573.55 6068.02,3557.67 v1(6069.13,3556.55) ; v1(5576.28,3404.55) 5551.24,3379.51 R76.1@5551.24,3373.4 5585.12,3339.53 U3.A1@5655.94,3339.53
GPMC0_BE1N_MUX: MOD1.44 R77.1 U3.B2 U7.36 | length 2022.3
  Top Layer w4: v1(5445.45,3434.5) 5446.96,3432.99 5446.96,3419.5 v1(5525.87,3340.58) ; MOD1.44@6034.29,3659.36 6034.29,3574.39 6040.08,3568.61 v1(6040.08,3564.82)
  Bottom Layer w4: v1(5525.87,3340.58) 5528.55,3337.91 5528.55,3330.65 5547.31,3311.9 R77.1@5551.24,3311.9 5562.94,3323.6 5671.87,3323.6 U3.B2@5685.47,3310 ; U7.36@5549.53,2756.84 5549.53,2800.23 5526.07,2823.68 5461.27,2823.68 5370.81,2914.14 5370.81,3181.59 5452.14,3262.91 5452.14,3425.16 5445.45,3431.84 5445.45,3544.18 5538.27,3637 5990.43,3637 6040.08,3587.35 v1(6040.08,3564.82)
GPMC0_CSN0_MUX: MOD1.45 R73.1 U3.B5 U4.38 | length 3409
  Top Layer w4: v1(5552.7,3149.6) 5552.7,3147.59 5571.62,3128.67 5617.47,3128.67 5665.89,3177.09 5665.89,3321.61 5628.6,3358.9 5580.98,3358.9 5514.93,3424.95 5514.93,3443.98 5539,3468.05 5539,3536.76 5586.56,3584.31 5895.11,3584.31 5983.79,3495.63 v1(6005.52,3495.63) 6005.91,3495.63 6016.98,3506.7 6016.98,3590.59 5984.29,3623.28 MOD1.45@5984.29,3659.36
  Bottom Layer w4: v1(5552.7,3149.6) 5552.7,3174.94 R73.1@5551.14,3176.5 5572.62,3176.5 5578.42,3170.7 5614.59,3170.7 5648.89,3205 5669.06,3205 U3.B5@5685.47,3221.42 ; v1(6005.52,3495.63) 5972.18,3495.63 5929.78,3538.03 5929.78,3595.22 5906,3619 5556.39,3619 5476.18,3538.79 5476.18,3217.23 5447.09,3188.14 5447.09,3031 5534.85,2943.24 5827.2,2943.24 5883.32,2887.12 5969.11,2887.12 6056.6,2799.62 6056.6,2757.25 U4.38@6056.2,2756.84
GPMC0_OEN_REN_MUX: MOD1.41 R75.1 U3.A2 U7.32 | length 2079.2
  Top Layer w4: v1(5413.9,3363.2) 5436.6,3363.2 5523.17,3276.63 v1(5541.09,3276.63) ; v1(6094.73,3560.33) 6114.39,3540.67 MOD1.41@6152.99,3540.66
  Bottom Layer w4: U7.32@5470.79,2756.84 5470.79,2777.6 5345.91,2902.48 5345.91,3222.63 5413.9,3290.62 5413.9,3364.07 5405.43,3372.54 5405.43,3612.88 5447.55,3655 6011.35,3655 6093.77,3572.58 6093.77,3561.28 v1(6094.73,3560.33) ; v1(5541.09,3276.63) 5543.13,3276.63 5543.91,3275.85 5544.64,3276.57 5556.44,3276.57 5589.86,3310 U3.A2@5655.94,3310 ; v1@5543.76,3275.7 5551.24,3268.21 R75.1@5551.24,3250.4
GPMC0_WAIT0_MUX: MOD1.47 U5.32 | length 2426.4
  Top Layer w4: MOD1.47@5884.29,3659.36 5884.29,3623.4 5958.75,3548.94 5991.78,3548.94 v1(5993.04,3547.68)
  Bottom Layer w4: U5.32@5003.49,2756.84 5003.49,3469.04 5211.45,3677 6120.04,3677 6148,3649.04 6148,3532.91 6125.42,3510.33 6043.82,3510.33 6006.46,3547.68 v1(5993.04,3547.68)
GPMC0_WEN_MUX: MOD1.42 R74.1 U3.G5 U7.38 | length 2815.6
  Top Layer w4: v1(5983.4,3099.02) 6003.17,3118.79 6187.58,3118.79 6224.97,3156.19 6224.97,3537.18 6171.49,3590.67 MOD1.42@6152.99,3590.66 v1(6103.33,3590.67)
  Bottom Layer w4: U7.38@5588.9,2756.84 5588.9,2763.73 U7.38@5591.82,2766.65 ; U7.38@5591.87,2766.65 5594.21,2769 5594.21,2792.36 5550.34,2836.24 5465.56,2836.24 5395.43,2906.38 5395.43,3175.21 5465.34,3245.13 5465.34,3542.1 5551.25,3628 5970.06,3628 6015,3583.06 6015,3560.6 6044.85,3530.75 6103.88,3530.75 6122.21,3549.09 6122.21,3571.32 6103.33,3590.2 v1(6103.33,3590.67) ; U3.G5@5833.11,3221.42 5819.1,3207.41 5819.1,3183.42 5856.52,3146 5917.69,3146 5933.53,3130.16 R74.1@5933.53,3089.9 5974.28,3089.9 v1(5983.4,3099.02)
GPMC0_WPN_MUX: MOD1.46 U5.29 | length 2666.4
  Top Layer w4: MOD1.46@5934.29,3659.36 5934.29,3625.95 5952.35,3607.89 5978.65,3607.89 5993.24,3593.31 v1(5993.24,3574.66)
  Bottom Layer w4: U5.29@4944.43,2756.84 4944.29,2756.99 4944.29,3600.9 5029.39,3686 6136.79,3686 6164.29,3658.5 6164.29,3517.93 6135.7,3489.34 6040.4,3489.34 6014.34,3515.41 5982.97,3515.41 5965.07,3533.31 5965.07,3560.51 5979.22,3574.66 v1(5993.24,3574.66)
HSEC_41: J2.41 J6.15 | length 695.9
  Top Layer w4: J6.15@1735,1239 1795.56,1299.56 1869.46,1299.56 2159.52,1589.62 J2.41@2159.52,1715.73
HSEC_43: J2.43 J6.16 | length 636.6
  Top Layer w4: J6.16@1835,1239 1856.11,1239 2191.02,1573.91 J2.43@2191.02,1715.73
HSEC_44: J2.44 J12.15 | length 771.4
  Top Layer w4: J12.15@1735,2329 1846,2329 1911,2329 2191.02,2048.98 J2.44@2191.02,1849.59
HSEC_45: J2.45 J6.17 | length 595.8
  Top Layer w4: J6.17@1935,1239 2222.52,1526.52 J2.45@2222.52,1715.73
HSEC_66: J2.66 J21.9 | length 1078.1
  Top Layer w4: J21.9@2207.95,2739 2207.95,2647.72 2663.46,2192.21 J2.66@2663.46,1849.59
HSEC_88: J2.88 J21.19 | length 971.4
  Top Layer w4: J2.88@3009.92,1849.59 3009.92,2396.55 3207.95,2594.58 J21.19@3207.95,2739
HSEC_96: J2.96 J21.23 | length 1084.9
  Top Layer w4: J2.96@3135.9,1849.59 3135.9,2168.26 3607.95,2640.31 J21.23@3607.95,2739
HSEC_113: J2.113 J20.29 | length 1321.9
  Top Layer w4: J2.113@3419.37,1715.73 3419.37,1542.07 3996.44,965 4163.6,965 4233.54,895.06 J20.29@4233.54,829
HSEC_114: J2.114 J21.30 | length 1333
  Top Layer w4: J2.114@3419.37,1849.59 3420,1850.22 3420,1980 4094.56,2654.56 4223.51,2654.56 J21.30@4307.95,2739
HSEC_115: J2.115 J20.30 | length 1418.1
  Top Layer w4: J2.115@3450.86,1715.73 3450.86,1544.52 3995.38,1000 4278.3,1000 4333.54,944.76 J20.30@4333.54,829
HSEC_116: J2.116 J21.31 | length 1392.4
  Top Layer w4: J2.116@3450.86,1849.59 3450.86,1963.88 4117.87,2630.89 4299.84,2630.89 J21.31@4407.95,2739
HSEC_117: J2.117 J20.31 | length 1464.6
  Top Layer w4: J2.117@3482.36,1715.73 3482.36,1560.05 4008.41,1034 4322.3,1034 4433.54,922.76 J20.31@4433.54,829
HSEC_119: J2.119 J20.32 | length 1496.6
  Top Layer w4: J2.119@3513.85,1715.73 3513.85,1581.15 4035,1060 4355.16,1060 4533.54,881.62 J20.32@4533.54,829
HSEC_136: J1.136 J25.8 | length 555.2
  Top Layer w4: J1.136@4563.78,1850.93 4563.78,1962.74 4561.86,1964.66 4561.86,2062.55 4773.04,2273.73 4809.73,2273.73 J25.8@4815,2279
HSEC_171: J1.171 J24.24 | length 1546
  Top Layer w4: J1.171@5130.71,1717.07 5130.71,1604.83 5180.79,1554.75 6104.25,1554.75 J24.24@6415,1244
HSEC_172: J1.172 J25.25 | length 1613.6
  Top Layer w4: J1.172@5130.71,1850.93 5130.71,1939.62 5205.25,2014.16 6250.16,2014.16 J25.25@6515,2279
HSEC_173: J1.173 J24.25 | length 1611.4
  Top Layer w4: J1.173@5162.2,1717.07 5162.2,1610.09 5205.77,1566.52 6192.48,1566.52 J24.25@6515,1244
HSEC_174: J1.174 J25.26 | length 1683.4
  Top Layer w4: J1.174@5162.2,1850.93 5162.2,1941.97 5206.03,1985.8 6321.8,1985.8 J25.26@6615,2279
HSEC_175: J1.175 J24.26 | length 1672.5
  Top Layer w4: J1.175@5193.7,1717.07 5193.7,1622.74 5237.43,1579.01 6279.99,1579.01 J24.26@6615,1244
HSEC_176: J1.176 J25.27 | length 1753.1
  Top Layer w4: J1.176@5193.7,1850.93 5193.7,1943.96 5219.56,1969.82 6405.82,1969.82 J25.27@6715,2279
HSEC_177: J1.177 J24.27 | length 1743.9
  Top Layer w4: J1.177@5225.2,1717.07 5225.2,1617.8 5248.88,1594.13 6364.87,1594.13 J24.27@6715,1244
HSEC_ADC0_AIN0: J2.9 J6.1 J18.1 J65.1 | length 2536.8
  Top Layer w4: J18.1@511.85,560.53 511.85,684.43 J65.1@675.16,847.74 675.16,854.14 604.3,925 489.56,925 382.1,1032.46 382.1,1191.9 J6.1@335,1239 677.8,1581.8 1631.8,1581.8 1655.59,1605.59 J2.9@1655.59,1715.73
HSEC_ADC0_AIN1: J2.11 J6.2 J22.1 J66.1 | length 2995.1
  Top Layer w4: J22.1@1470,549.3 1470,579.6 1279.46,770.14 J66.1@1279.46,852.31 1279.46,882.24 1192.59,969.11 575.92,969.11 481.85,1063.18 481.85,1192.15 J6.2@435,1239 445.15,1239 765.95,1559.8 1643.7,1559.8 1687.08,1603.18 J2.11@1687.08,1715.73
HSEC_ADC0_AIN2: J2.15 J6.4 | length 1392.6
  Top Layer w4: J6.4@635,1239 935.56,1539.56 1710.54,1539.56 1750.07,1579.09 J2.15@1750.07,1715.73
HSEC_ADC0_AIN3: J2.17 J6.5 | length 1325.6
  Top Layer w4: J6.5@735,1239 1011.56,1515.56 1720.56,1515.56 1781.57,1576.57 J2.17@1781.57,1715.73
HSEC_ADC0_AIN4: J2.21 J6.6 | length 1279.3
  Top Layer w4: J6.6@835,1239 1087.56,1491.56 1743.67,1491.56 1844.56,1592.45 J2.21@1844.56,1715.73
HSEC_ADC0_AIN5: J2.23 J6.7 | length 1212.2
  Top Layer w4: J6.7@935,1239 1163.56,1467.56 1753.61,1467.56 1876.06,1590 J2.23@1876.06,1715.73
HSEC_ADC1_AIN0: J2.12 J12.1 | length 1662.6
  Top Layer w4: J12.1@335,2329 335,2255 603.58,1986.42 1667.39,1986.42 1687.08,1966.73 J2.12@1687.08,1849.59
HSEC_ADC1_AIN1: J2.14 J12.2 | length 1553.9
  Top Layer w4: J12.2@435,2329 751.58,2012.42 1678.16,2012.42 1718.58,1972 J2.14@1718.58,1849.59
HSEC_ADC1_AIN2: J2.18 J12.4 | length 1425.7
  Top Layer w4: J12.4@635,2329 925.58,2038.42 1696.58,2038.42 1730.17,2038.42 1781.57,1987.02 1781.57,1953.43 J2.18@1781.57,1849.59
HSEC_ADC1_AIN3: J2.20 J12.5 | length 1366.5
  Top Layer w4: J12.5@735,2329 999.58,2064.42 1718,2064.42 1751.59,2064.42 1813.07,2002.95 1813.07,1969.35 J2.20@1813.07,1849.59
HSEC_ADC1_AIN4: J2.24 J12.6 | length 1333.9
  Top Layer w4: J12.6@835,2329 1073.58,2090.42 1737.73,2090.42 1796.22,2090.42 1876.06,2010.58 1876.06,1952.09 J2.24@1876.06,1849.59
HSEC_ADC1_AIN5: J2.26 J12.7 | length 1270.9
  Top Layer w4: J12.7@935,2329 935,2325 1143.58,2116.42 1806.99,2116.42 1907.56,2015.85 J2.26@1907.56,1849.59
HSEC_ADC2_AIN0: J2.31 J6.11 | length 931.5
  Top Layer w4: J6.11@1335,1239 1491.93,1395.93 1796.53,1395.93 2002.04,1601.44 J2.31@2002.04,1715.73
HSEC_ADC2_AIN1: J2.33 J6.12 | length 864.4
  Top Layer w4: J6.12@1435,1239 1567.56,1371.56 1806.1,1371.56 2033.54,1598.99 J2.33@2033.54,1715.73
HSEC_ADC2_AIN2: J2.37 J6.13 | length 826
  Top Layer w4: J6.13@1535,1239 1643.56,1347.56 1842.65,1347.56 2096.53,1601.44 J2.37@2096.53,1715.73
HSEC_ADC2_AIN3: J2.39 J6.14 | length 758.9
  Top Layer w4: J6.14@1635,1239 1719.56,1323.56 1852.59,1323.56 2128.03,1598.99 J2.39@2128.03,1715.73
HSEC_ADC3_AIN0: J2.28 J12.8 | length 1203.1
  Top Layer w4: J12.8@1035,2329 1221.58,2142.42 1817.76,2142.42 1939.05,2021.13 J2.28@1939.05,1849.59
HSEC_ADC3_AIN1: J2.30 J12.9 | length 1137.7
  Top Layer w4: J12.9@1135,2329 1289,2175 1763.46,2175 1821.95,2175 1970.55,2026.4 1970.55,1967.91 J2.30@1970.55,1849.59
HSEC_ADC3_AIN2: J2.34 J12.11 | length 1003.7
  Top Layer w4: J12.11@1335,2329 1463,2201 1784,2201 1864,2201 2033.54,2031.46 2033.54,1951.46 J2.34@2033.54,1849.59
HSEC_ADC3_AIN3: J2.36 J12.12 | length 938.1
  Top Layer w4: J12.12@1435,2329 1537,2227 1813,2227 1874.5,2227 2065.04,2036.46 2065.04,1974.96 J2.36@2065.04,1849.59
HSEC_ADC3_AIN4: J2.40 J12.13 | length 890
  Top Layer w4: J12.13@1535,2329 1613,2251 1894.53,2251 2128.03,2017.5 J2.40@2128.03,1849.59
HSEC_ADC3_AIN5: J2.42 J12.14 | length 829.1
  Top Layer w4: J12.14@1635,2329 1636,2329 1684,2281 1847,2281 1909,2281 2159.52,2030.48 2159.52,1968.48 J2.42@2159.52,1849.59
HSEC_ADC4_AIN0: J2.25 J6.8 | length 1145.1
  Top Layer w4: J6.8@1035,1239 1239.56,1443.56 1763.56,1443.56 1907.56,1587.56 J2.25@1907.56,1715.73
HSEC_ADC4_AIN1: J2.27 J6.9 | length 1084.6
  Top Layer w4: J6.9@1135,1239 1315.56,1419.56 1784.67,1419.56 1939.05,1573.93 J2.27@1939.05,1715.73
HSEC_EPWM3_B: J2.56 J21.4 | length 1167.8
  Top Layer w4: J21.4@1707.95,2739 2380,2066.95 J2.56@2380,1849.59
HSEC_EPWM4_A: J2.57 J20.5 | length 1261.2
  Top Layer w4: J20.5@1833.54,829 1833.54,844.32 1890,900.78 2031.46,900.78 2537.48,1406.8 J2.57@2537.48,1715.73
HSEC_EPWM4_B: J2.59 J20.6 | length 1200.5
  Top Layer w4: J20.6@1933.54,829 1981.32,876.78 2067.61,876.78 2568.97,1378.14 J2.59@2568.97,1715.73
HSEC_EPWM5_A: J2.61 J20.7 | length 1143.9
  Top Layer w4: J20.7@2033.54,829 2071.73,829 2600.47,1357.74 J2.61@2600.47,1715.73
HSEC_EPWM5_B: J2.63 J20.8 | length 1098.8
  Top Layer w4: J20.8@2133.54,829 2143.1,829 2631.96,1317.86 J2.63@2631.96,1715.73
HSEC_EPWM6_A: J2.58 J21.5 | length 1191.6
  Top Layer w4: J21.5@1807.95,2739 2537.48,2009.47 J2.58@2537.48,1849.59
HSEC_EPWM6_B: J2.60 J21.6 | length 1163.2
  Top Layer w4: J21.6@1907.95,2739 1907.95,2694.96 2568.97,2033.94 J2.60@2568.97,1849.59
HSEC_EPWM7_A: J2.62 J21.7 | length 1134.8
  Top Layer w4: J21.7@2007.95,2739 2007.95,2647.05 2600.47,2054.53 J2.62@2600.47,1849.59
HSEC_EPWM7_B: J2.64 J21.8 | length 1106.5
  Top Layer w4: J21.8@2107.95,2739 2107.95,2624.28 2631.96,2100.27 J2.64@2631.96,1849.59
HSEC_EPWM21_A: J2.89 J20.19 | length 968.8
  Top Layer w4: J2.89@3041.41,1718.18 3041.41,1339.36 3233.54,1147.24 J20.19@3233.54,829
HSEC_EPWM21_B: J2.90 J21.20 | length 999.8
  Top Layer w4: J2.90@3041.41,1849.59 3041.41,2341.44 3307.95,2607.98 J21.20@3307.95,2739
HSEC_EQEP0_A: J2.102 J21.25 | length 1129
  Top Layer w4: J2.102@3230.39,1849.59 3230,1849.98 3230,2030 3807.95,2607.95 J21.25@3807.95,2739
HSEC_EQEP0_B: J2.100 J21.24 | length 1100.3
  Top Layer w4: J2.100@3198.89,1849.59 3198.89,2090 3707.95,2599.06 J21.24@3707.95,2739
HSEC_EQEP0_INDEX: J2.106 J21.27 | length 1185.4
  Top Layer w4: J2.106@3293.38,1849.59 3293.38,1993.38 4007.95,2707.95 J21.27@4007.95,2739
HSEC_EQEP0_STROBE: J2.104 J21.26 | length 1157
  Top Layer w4: J2.104@3261.89,1849.59 3261.89,2006.89 3907.95,2652.95 J21.26@3907.95,2739
HSEC_EQEP1_INDEX: J2.74 J21.13 | length 964.6
  Top Layer w4: J21.13@2607.95,2739 2607.95,2605.36 2789.44,2423.87 J2.74@2789.44,1849.59
HSEC_EQEP1_STROBE: J2.72 J21.12 | length 993
  Top Layer w4: J21.12@2507.95,2739 2507.95,2601.88 2757.95,2351.88 J2.72@2757.95,1849.59
HSEC_EQEP2_A: J2.92 J21.21 | length 1028.2
  Top Layer w4: J2.92@3072.91,1849.59 3072.91,2281.85 3407.95,2616.89 J21.21@3407.95,2739
HSEC_EQEP2_B: J2.93 J20.21 | length 1023.1
  Top Layer w4: J2.93@3104.41,1715.73 3104.41,1398.46 3433.54,1069.33 J20.21@3433.54,829
HSEC_GPIO43: J2.49 J20.1 R8.2 U1.14 | length 5157.2
  Top Layer w4: J20.1@1433.54,829 1614.54,1010 2004.91,1010 2285.51,1290.59 J2.49@2285.51,1715.73 ; U1.14@4440.64,379.98 4440.27,380.35 4440.93,381.01 v1(4440.93,459.79) 4526.97,459.79 R8.2@4528.78,461.6
  Bottom Layer w4: J20.1@1433.54,829 1433.54,698.62 1683.23,448.93 2707.71,448.93 2818.46,338.18 3837.06,338.18 3947.81,448.93 4074.69,448.93 4234.48,289.14 4356.01,289.14 4440.93,374.06 v1(4440.93,459.79)
HSEC_GPIO44: J2.51 J20.2 R14.1 R22.2 U4.8 U5.8 U6.8 U7.8 | length 7156.2
  Top Layer w4: J20.2@1533.54,829 1690.54,986 2014.85,986 2317,1288.15 2317,1590.12 v1(2316.75,1590.37) 2317,1590.62 J2.51@2317,1715.73 ; v1(4784.62,2599.77) 4828.73,2599.77 4835.87,2606.91 4861.8,2606.91 4881.95,2586.76 4965.02,2586.76 v1(4982.71,2604.45) 5448.4,2604.45 v1(5452.14,2600.71) ; v1(5396.68,2470.82) 5611.22,2470.82 5703.98,2563.58 5796.11,2563.58 5825.14,2592.61 5870.37,2592.61 5875,2587.98 v1(5908.75,2587.98) 5895.27,2574.5 R22.2@5895.27,2537.19 ; R14.1@5851.61,2536.98 5895.06,2536.98 R22.2@5895.27,2537.19 ; v1(6121.53,2504.63) 6120.94,2504.63 6088.38,2537.19 R22.2@5895.27,2537.19
  Bottom Layer w4: v1(2316.75,1590.37) 2316.75,2379.06 2656.81,2719.12 2656.81,2770.03 2682.56,2795.78 4625.38,2795.78 4686.95,2734.21 4686.95,2662.25 4749.43,2599.77 v1(4784.62,2599.77) ; v1(4982.71,2604.45) 4982.71,2625.83 U5.8@4983.8,2626.92 ; v1(5396.68,2470.82) 5452.14,2526.28 v1(5452.14,2600.71) 5452.14,2625.89 U7.8@5451.1,2626.92 ; v1(5908.75,2587.98) 5908.75,2589.89 5918.4,2599.54 U4.8@5918.4,2626.92 ; v1(6121.53,2504.63) 6297.97,2504.63 6385.71,2592.36 U6.8@6385.71,2626.92
HSEC_GPIO45: J2.53 J20.3 MOD1.48 | length 8082.9
  Top Layer w4: J20.3@1633.54,829 1753.32,948.78 2011.58,948.78 2348.15,1285.36 2348.15,1715.39 J2.53@2348.5,1715.73 ; v1(3709.48,2985.91) 3709.8,2986.23 3709.8,3501.19 3938.82,3730.21 5802.82,3730.21 5834.29,3698.74 MOD1.48@5834.29,3659.36 MOD1.48@5833.88,3658.95
  Bottom Layer w4: J20.3@1633.54,829 1648.22,829 1831.5,1012.28 1925.95,1012.28 2020.92,1107.25 2020.92,2623.76 2067.17,2670.01 2067.17,2846.35 2206.73,2985.91 v1(3709.48,2985.91)
HSEC_GPIO46: J2.55 J20.4 MOD1.50 | length 7879
  Top Layer w4: J20.4@1733.54,829 1829.32,924.78 2021.52,924.78 2379.65,1282.91 2379.65,1715.39 J2.55@2380,1715.73 ; v1(3770.47,2986.71) 3770.47,3506.33 3984.35,3720.21 5717.84,3720.21 5734.29,3703.76 MOD1.50@5734.29,3659.36 MOD1.50@5733.54,3658.61
  Bottom Layer w4: J20.4@1733.54,829 1844.93,940.39 2019.55,940.39 2163.69,1084.53 2163.69,2887.49 2243.24,2967.04 3752.16,2967.04 3770.47,2985.35 v1(3770.47,2986.71)
HSEC_GPIO47: J2.50 J21.1 R13.1 R20.2 U4.9 U4.10 U7.9 U7.10 | length 6571.1
  Top Layer w4: J21.1@1407.95,2739 1593.84,2553.11 1777.55,2553.11 2255.46,2075.2 v1(2255.46,1994.05) 2285.51,1964 J2.50@2285.51,1849.59 ; v1(4769.21,2644.59) 4768,2643.38 4768,2616.89 4765.75,2614.64 4765.75,2591.95 4790.94,2566.76 5120.81,2566.76 v1(5151.21,2536.36) ; v1(5366.47,2470.15) 5400.94,2435.68 5708.73,2435.68 5734.3,2461.25 5734.3,2531.29 5740.97,2537.96 R20.2@5767.99,2537.96 5768.33,2537.62 R13.1@5809.01,2537.62 5809.01,2557.51 5825.24,2573.74 v1(5862.55,2573.74)
  Bottom Layer w4: v1(2255.46,1994.05) 2255.46,2618.58 2359.21,2722.33 2359.21,2747.93 2446.69,2835.41 3808.74,2835.41 3832.07,2858.74 3902.61,2858.74 3919.86,2841.49 4458.07,2841.49 4492.85,2806.71 4684.85,2806.71 4732.47,2759.09 4732.47,2677.06 4768.03,2641.5 4769.21,2642.68 v1(4769.21,2644.59) ; v1(5151.21,2536.36) 5152.69,2537.84 5298.77,2537.84 v1(5366.47,2470.15) ; U7.10@5411.73,2626.92 5411.73,2572.24 5366.47,2526.98 v1(5366.47,2470.15) ; U7.9@5431.42,2626.92 5431.42,2535.1 v1(5366.47,2470.15) ; U4.10@5879.03,2626.92 5879.03,2603.63 5862.55,2587.15 v1(5862.55,2573.74) 5867.82,2573.74 5898.72,2604.64 U4.9@5898.72,2626.92
HSEC_GPIO48: J2.52 J21.2 U6.16 | length 6465.1
  Top Layer w4: J21.2@1507.95,2739 1651.06,2595.89 1771.53,2595.89 2291.76,2075.66 v1(2291.76,1999.08) 2317,1973.84 J2.52@2317,1849.59 ; v1(3862.05,2822.3) 3862.99,2821.36 4395.08,2821.36 4453.22,2763.22 4453.22,2489.36 4453.93,2488.65 4453.93,2485.07 4611.27,2327.73 4725.32,2327.73 4725.38,2327.67 5612.57,2327.67 5618.22,2322.02 5670.78,2322.02 v1(5671.83,2323.08)
  Bottom Layer w4: v1(2291.76,1999.08) 2291.76,2552.32 2465.33,2725.89 2465.33,2776.93 2496.9,2808.5 3848.25,2808.5 v1(3862.05,2822.3) ; v1(5671.83,2323.08) 5671.98,2323.08 5713,2364.09 5851.64,2365.47 5853.28,2365.48 5854.43,2366.64 5856.1,2368.3 5961.74,2473.94 5961.74,2523.86 6031.09,2593.21 6218.09,2593.21 6228.22,2603.34 U6.16@6228.22,2626.92
HSEC_GPIO49: J2.54 J21.3 R9.2 U1.11 | length 6817.9
  Top Layer w4: v1(1286.62,2397.14) 1286.62,2711.86 1363.42,2788.66 1558.29,2788.66 1686.43,2660.51 1749.66,2660.51 2348.5,2061.68 J2.54@2348.5,1849.59 ; U1.11@4290.64,379.98 4290.64,330.78 v1(4290.13,330.27) 4290.13,289.79 R9.2@4291.3,288.62
  Bottom Layer w4: v1(1286.62,2397.14) 1286.62,1543.16 1407.37,1422.41 1423.04,1422.41 1483.29,1362.16 1483.29,762.4 1552.07,693.62 1695.55,693.62 1914.89,474.28 2706.72,474.28 2819.02,361.98 3822.95,361.98 3935.25,474.28 4146.12,474.28 v1(4290.13,330.27)
HSEC_GPIO65: J2.86 J21.18 | length 943.1
  Top Layer w4: J2.86@2978.42,1849.59 2978.42,2450.53 3107.95,2580.06 J21.18@3107.95,2739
